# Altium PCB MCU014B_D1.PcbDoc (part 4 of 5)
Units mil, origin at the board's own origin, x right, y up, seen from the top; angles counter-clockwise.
Board outline 2300.04 x 4058 mil, 4 copper layers (TOP, GND, PWR, BOTTOM), stack 48.84 mil thick; 371 components, 238 nets, 1148 pads, 688 vias.
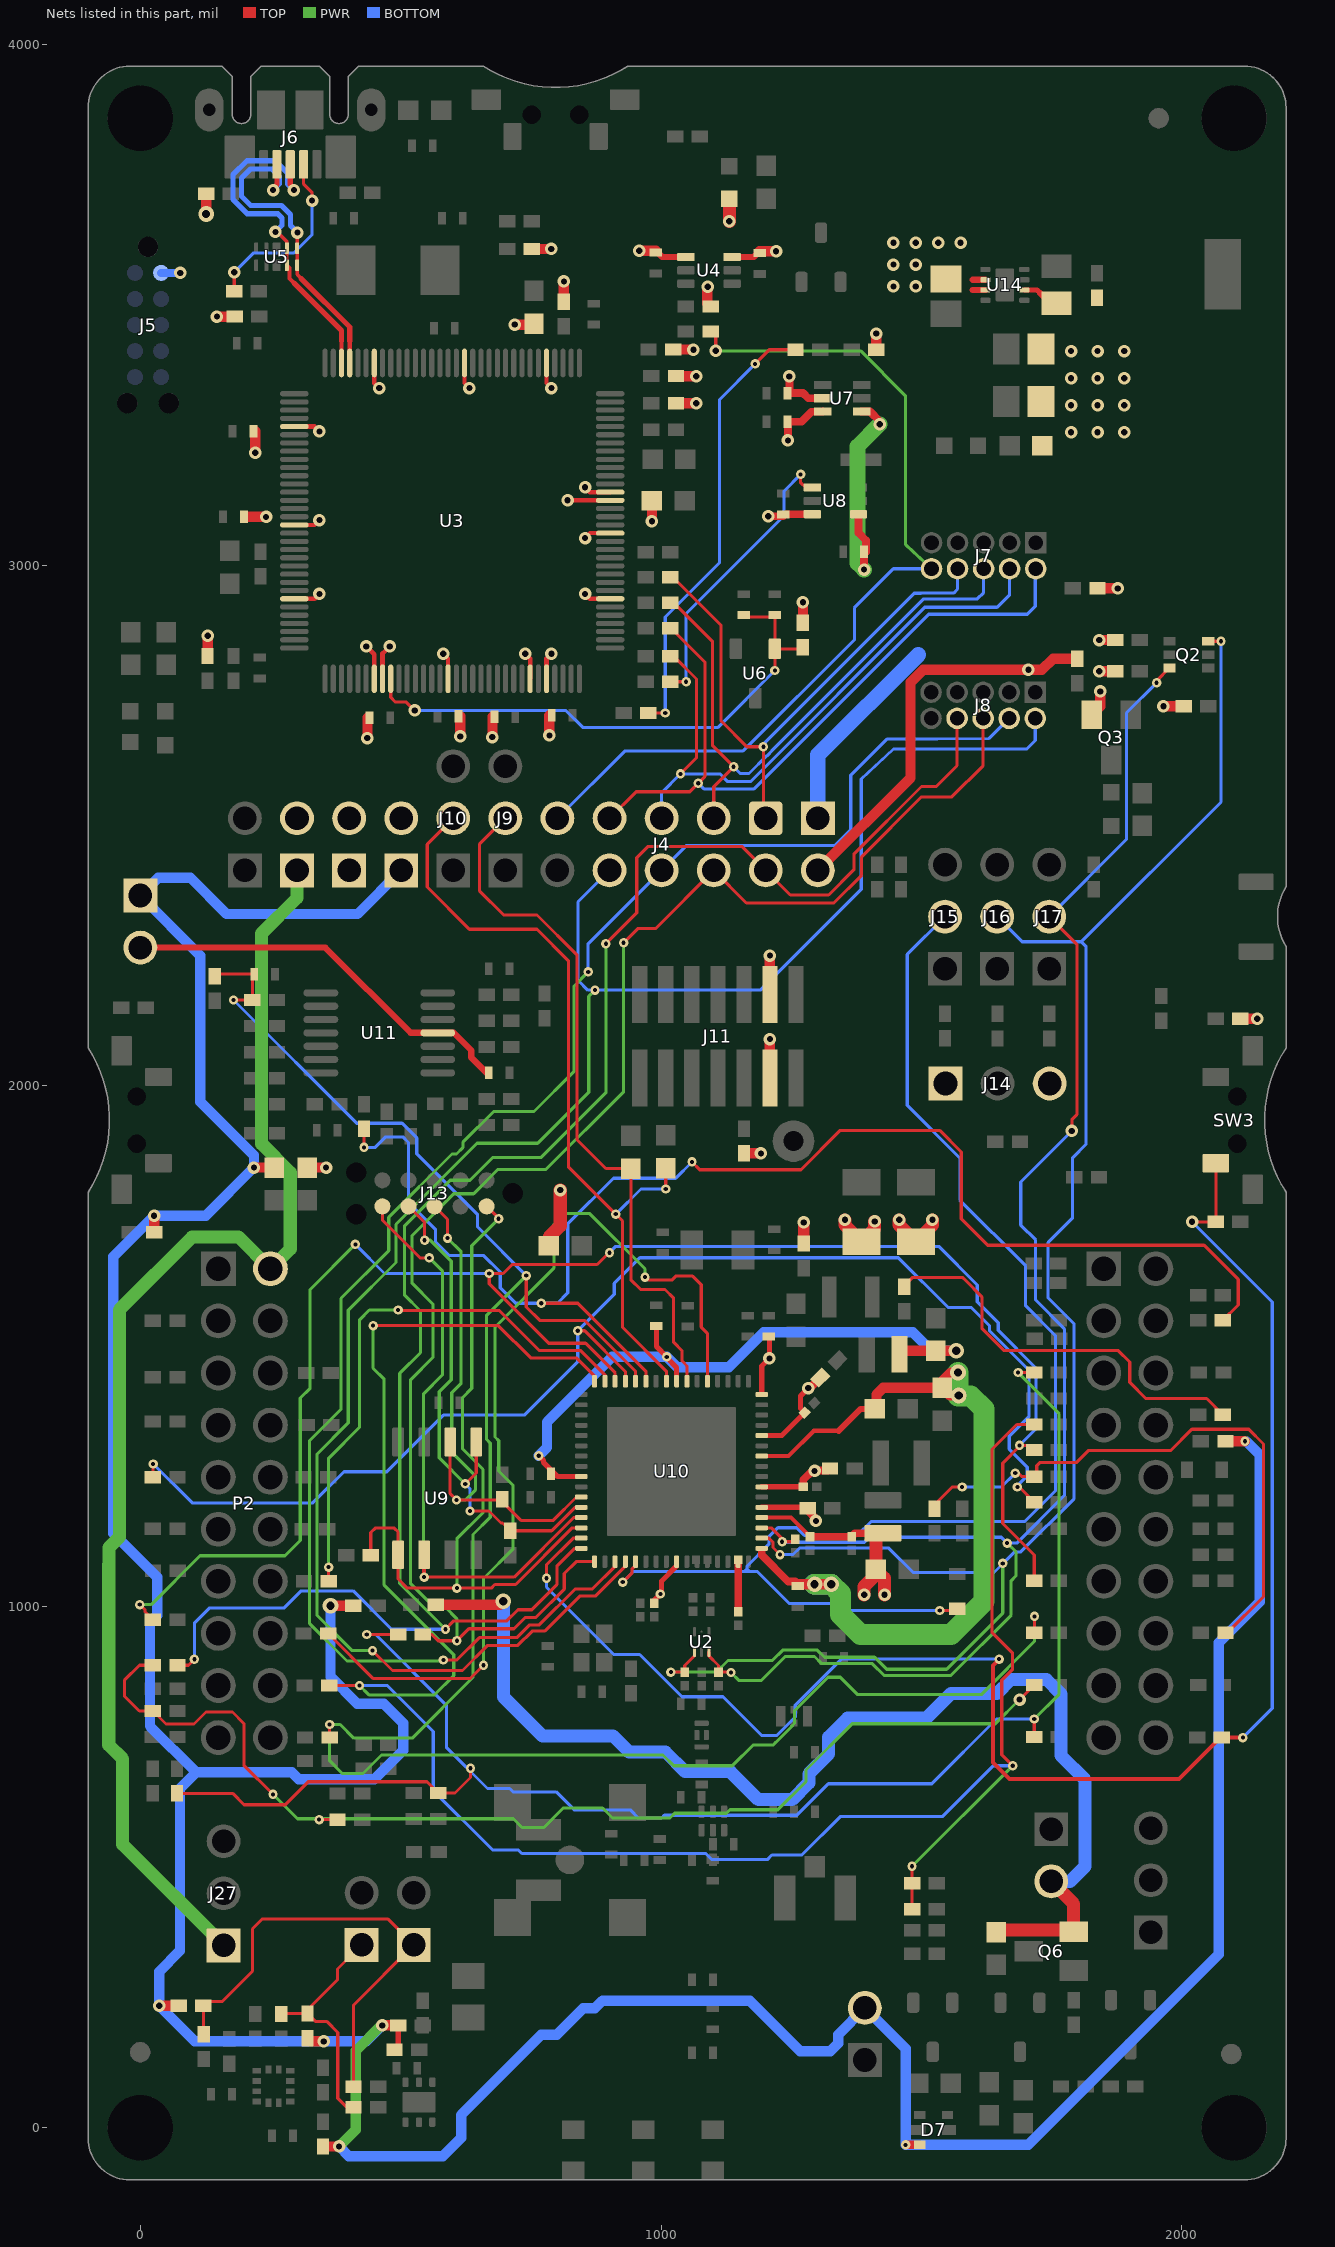
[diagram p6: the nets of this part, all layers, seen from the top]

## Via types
v1: diameter 24, hole 12, TOP to BOTTOM, tented both sides, 230 vias
v2: diameter 18, hole 8, TOP to BOTTOM, tented both sides, 218 vias
v3: diameter 20, hole 10, TOP to BOTTOM, tented both sides, 159 vias
v4: diameter 19.68, hole 7.87, TOP to BOTTOM, 32 vias
v5: diameter 20, hole 8, TOP to BOTTOM, tented both sides, 24 vias
v6: diameter 30, hole 16, TOP to BOTTOM, tented both sides, 17 vias
v7: diameter 20, hole 8, TOP to BOTTOM, tented bottom, 4 vias
v8: diameter 19.68, hole 7.87, TOP to BOTTOM, tented bottom, 4 vias

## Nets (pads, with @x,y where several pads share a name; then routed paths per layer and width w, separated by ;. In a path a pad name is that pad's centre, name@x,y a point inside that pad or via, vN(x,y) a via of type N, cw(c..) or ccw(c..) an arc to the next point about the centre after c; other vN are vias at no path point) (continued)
P15_GPIO_22: R95.2 R157.1 SW3.3 U10.15 | length 3157.5
  TOP w6: v2(780,1055) 780,1081 831.05,1132.05 U10.15@846.77,1132.05 ; v1(2019.38,1739.21) R157.1@2065.02,1739.21 SW3.3@2065.02,1851.92
  TOP w8: v2(1648.92,899.64) 1637,887.72 1637,701.43 1669.21,669.21 1994.21,669.21 2073.99,748.99 R95.2@2076.62,748.99 v2(2117,748.99)
  BOTTOM w6: v2(780,1055) 780,1037.78 909.2,908.58 958.85,908.58 1040,827.43 1118.93,827.43 1193.62,752.75 1221.64,752.75 1257.48,788.59 1257.48,811.22 1345.9,899.64 v2(1648.92,899.64) ; v1(2019.38,1739.21) 2173.35,1585.25 2173.35,805.34 v2(2117,748.99)
P16_GPIO_23: R50.2 R90.1 R108.1 R135.1 | length 2192
  TOP w6: R50.2@24.38,888 -1.31,888 -30.39,858.92 -30.39,828.81 -1.7,800.11 24.27,800.11 R108.1@24.38,800 49.38,775 103.2,775 126.2,798 177,798 199,776 199,696 v2(255,640) ; v2(343.38,591.52) R135.1@378.76,591.52 ; v1(1688.19,822.05) 1688.43,822.05 R90.1@1716.38,850
  PWR w6: v2(255,640) 301.93,593.07 716.7,593.07 733.6,576.17 774.55,576.17 812.06,613.68 887.7,613.68 906.78,594.59 1017.07,594.59 1026.15,603.67 1125.51,603.67 1132.35,610.52 1224.19,610.52 1278.19,664.52 1278.19,686.9 1366.84,775.55 1641.69,775.55 v1(1688.19,822.05)
P16_JTAG_TDI: J4.2 J8.8 R50.1 U10.16 | length 3672.8
  TOP w6: R50.1@71.62,888 92.65,888 v2(103.93,899.28) ; v2(586,957) 602,973 703.91,973 725.23,994.32 751.72,994.32 800,1042.6 800,1078 834.36,1112.36 U10.16@846.77,1112.36 ; v2(894,2273) 953.37,2332.37 953.37,2438.37 975,2460 1155,2460 J4.2@1201,2414 1248.27,2366.73 1321.73,2366.73 1370,2415 1370,2445 1500,2575 1528.24,2575 1568.24,2615 J8.8@1568.24,2705.73
  PWR w6: v2(586,957) 498.21,1044.79 498.21,1448.21 538,1488 538,1568 507,1599 507,1731 595,1819 633.14,1819 677.14,1863 770,1863 894,1987 v2(894,2273)
  BOTTOM w6: v2(103.93,899.28) 103.93,968.75 133.18,998 276.52,998 309.19,1030.67 408.69,1030.67 482.36,957 v2(586,957)
P17_GPIO_24: R54.2 R70.1 R94.1 R109.1 R142.1 | length 3026.1
  TOP w6: R109.1@70.4,641.89 177.43,641.89 199.33,620 278.43,620 322.64,664.21 550.55,664.21 R142.1@572.24,642.52 604.28,642.52 634.09,672.33 v2(634.09,690) ; v2(435,947) R54.2@495,947 ; v2(1685.45,1450) R70.1@1716.38,1450 ; R94.1@1716.38,750 v2(1716.38,784.6)
  PWR w6: v2@1685.45,1449.13 1764.17,1370.41 1764.17,832.39 v2(1716.38,784.6)
  BOTTOM w6: v2(435,947) 451.84,947 587.67,811.16 587.67,730.33 666.79,651.21 709.18,651.21 715.66,644.74 798.39,644.74 832.94,610.19 940.81,610.19 956.62,594.39 1000.84,594.39 1006.36,599.91 1260.74,599.91 1321.25,660.42 1519.8,660.42 1643.97,784.6 v2(1716.38,784.6)
P17_JTAG_TDO: J4.4 J8.6 R54.1 U10.17 | length 3077.9
  TOP w6: R54.1@542.24,947 560,947 572,935 v2(608,935) 631,958 717.48,958 739.1,979.62 759.62,979.62 814,1034 814,1064 836.77,1086.77 U10.17@872.36,1086.77 ; v2(928,2275) 955.21,2302.21 989.21,2302.21 J4.4@1101,2414 1163.64,2351.36 1331.62,2351.36 1385,2404.75 1385,2440 1500,2555 1558.24,2555 1618.24,2615 J8.6@1618.24,2705.73
  PWR w6: v2(608,935) 608,977 586,999 564.43,999 519.21,1044.22 519.21,1436.21 562,1479 562,1581 522,1621 522,1713 602,1793 640,1793 687,1840 779,1840 928,1989 v2(928,2275)
P19_JTAG_TCK: J4.6 J8.4 U10.19 | length 3325.3
  TOP w6: v2(582,898) 608,898 651,941 723.12,941 747.49,965.37 766.37,965.37 835.22,1034.21 867.82,1034.21 911.73,1078.12 U10.19@911.73,1086.77
  PWR w6: v2(582,898) 580,896 397,896 325.31,967.69 325.31,1319.31 385.34,1379.34 385.34,1592.34 477,1684 477,1747.76 598.68,1869.44 607.19,1869.44 619.49,1881.74 619.49,1891.75 678.75,1951 756,1951 833,2028 833,2192 v2(860,2219)
  BOTTOM w6: v2(860,2219) 860,2273 J4.6@1001,2414 1049,2462 1334.14,2462 1364.21,2492.07 1364.21,2596.57 1433.43,2665.79 1629.85,2667.34 J8.4@1668.28,2705.77
P20_JTAG_TMS: J4.8 J8.2 U10.20 | length 3702.6
  TOP w6: v2(446,916) 484.25,877.75 618.75,877.75 667,926 725.09,926 752.46,953.37 776.31,953.37 843.48,1020.54 873.78,1020.54 931.42,1078.18 U10.20@931.42,1086.77
  PWR w6: v2(446,916) 407,916 339.31,983.69 339.31,1293.31 399.41,1353.41 399.41,1569.41 491,1661 491,1734.42 646.58,1890 763,1890 861,1988 861,2172 v2(873,2184)
  BOTTOM w6: J4.8@901,2414 840.57,2353.57 840.57,2202.89 859.47,2184 v2(873,2184) 1190.58,2184 1384.21,2377.64 1384.21,2589.33 1446.05,2647 1701.9,2647 1718.28,2663.38 J8.2@1718.28,2705.77
P21_GPIO_25: R55.2 R75.1 R87.2 | length 1123.7
  TOP w6: R55.2@1525,1188.62 1525,1196 1559,1230 v2(1578,1230) ; v2(1679.81,1256.81) 1686.19,1256.81 1693,1250 R75.1@1716.38,1250 1721.1,1250 1721.1,1271.1 1727,1277 1797,1277 1820,1300 1978.09,1300 2019.09,1341 2128.2,1341 2156.66,1312.53 2156.66,1019.63 2087.03,950 R87.2@2083.62,950
  BOTTOM w6: v2(1578,1230) 1653,1230 v2(1679.81,1256.81)
P45_GPIO_31: R47.1 R73.2 | length 787.5
  TOP w6: R47.1@1467,1614.62 1467,1617 1482,1632 1579.39,1632 1583.98,1627.4 1615.89,1595.15 1615.89,1534.77 1658.69,1491.97 1877.78,1491.97 1899.79,1469.96 1899.79,1430.89 1930.54,1400.14 2047.48,1400.14 R73.2@2078.62,1369
P53_GPIO_30: R97.2 U10.53 | length 1830.2
  TOP w6: R97.2@360.62,949 447.52,862.1 633.1,862.1 v2(659,888) ; v2(969,1633) 974.62,1627.38 1020.38,1627.38 1028,1635 1060.53,1635 1077,1618.53 1077,1537 1088.9,1525.1 U10.53@1088.9,1433.23
  PWR w6: v2(659,888) 659,1054.57 716,1111.57 716,1233 688.21,1260.79 688.21,1318.91 681,1326.13 681,1537 794.21,1650.21 794.21,1734.21 815,1755 863,1755 969,1649 v2(969,1633)
P55_GPIO_01: J9.2 R39.1 U10.55 | length 1359.7
  TOP w6: J9.2@701,2514 651,2464 651,2375.1 697.69,2328.41 761.81,2328.41 838.21,2252.01 838.21,1897.21 893.92,1841.5 R39.1@942,1841.5 942,1628 960.63,1609.37 1007.36,1609.37 1024,1592.74 1024,1508 1040,1492 1040,1472.26 1045.84,1466.42 1045.84,1466.16 1049.53,1462.47 U10.55@1049.53,1433.23
P57_GPIO_02: J10.2 R38.1 U10.57 | length 1523.9
  TOP w5.98: 822,1845 822,2240.73
  TOP w6: J10.2@601,2514 551,2464 551,2381.98 631.96,2301.01 761.71,2301.01 822,2240.73 ; 822,1845 v2(913,1754) 926,1741 926,1536.72 1010.16,1452.56 U10.57@1010.16,1433.23 ; v2(1009,1802.32) R38.1@1009,1842.5
  BOTTOM w6: v2(913,1754) 961.32,1802.32 v2(1009,1802.32)
P59_GPIO_04: R65.2 R125.2 U10.59 | length 2739.8
  TOP w6: v2(429.54,1882.2) 429.64,1882.3 R125.2@429.64,1917.76 ; v2(770,1583) 840.12,1583 970.79,1452.33 U10.59@970.79,1433.23 ; v2(1059.21,1854.21) 1074.21,1839.21 1268.51,1839.21 1344.06,1914.76 1534.66,1914.76 1576.21,1873.21 1576.21,1745 1627,1694.21 2042.58,1694.21 2108.14,1628.66 2108.14,1579.52 R65.2@2078.62,1550
  BOTTOM w6: v2(429.54,1882.2) 451.24,1882.2 471.42,1902.38 503.93,1902.38 514.92,1891.38 514.92,1776.53 567.16,1724.28 567.16,1700.61 593.56,1674.21 659.83,1674.21 691.15,1642.89 691.15,1612.46 720.61,1583 v2(770,1583) 801.03,1583 820.79,1602.76 820.79,1735.25 908.49,1822.95 1027.95,1822.95 v2(1059.21,1854.21)
P60_GPIO_05: C71.1 R86.1 R106.2 R113.1 R114.2 U10.60 | length 4170.6
  TOP w6: R113.1@143,2210.62 147.38,2215 215.38,2215 R114.2@215.38,2165 v2(179,2165) ; R106.2@363.62,749 v2(363.62,774.21) ; v2(741.02,1636) 741.02,1575.72 766.73,1550 853.02,1550 951.1,1451.92 U10.60@951.1,1433.23 ; R86.1@1716.38,950 1716.94,950.56 v2(1716.94,981.63)
  PWR w6: v2(741.02,1636) 665,1560 665,1321.43 672,1314.43 672,1171.8 639,1138.8 639,864.73 522.15,747.88 410.21,747.88 383.88,774.21 v2(363.62,774.21) 363.62,704.26 387.74,680.14 427.73,680.14 463.09,715.51 1003.61,715.51 1024.25,694.87 1136.68,694.87 1176.37,734.56 1214.73,734.56 1220.25,740.08 1220.59,740.08 1249.7,769.19 1249.7,769.53 1256.18,776.01 1256.18,800.53 1320.52,864.87 1344.16,864.87 1377.66,831.37 1614.58,831.37 1716.94,933.73 v2(1716.94,981.63)
  BOTTOM w6: v2(179,2165) 415.48,1928.52 502.87,1928.52 530.89,1900.49 530.89,1869.8 647.85,1752.84 647.85,1729.16 v2(741.02,1636)
P61_GPIO_06: R84.1 R107.1 U10.61 | length 2525.5
  TOP w6: R84.1@24.81,1249.03 v2(24.81,1274.24) ; v2(840,1530) 853.2,1530 931.42,1451.78 U10.61@931.42,1433.23 ; v2(1684,1230) 1687.38,1230 R107.1@1716.38,1201
  BOTTOM w6: v2(24.81,1274.24) 99.52,1199.53 331.3,1199.53 391.11,1259.35 473.35,1259.35 582,1368 737.28,1368 840,1470.72 ; 840,1470.08 840,1470.72 ; v2@1685,1230 v2(1684,1230) 1684,1232.72 1703,1251.72 1703,1268.28 1668.45,1302.83 1668.45,1327.67 1706.59,1365.81 1706.59,1453.89 1630.82,1529.66 1630.82,1539.22 1595.05,1575 1550.93,1575 1455.62,1670.31 959.32,1670.31 910,1621 910,1600.01 v2(840,1530) 840,1470.72
P62_GPIO_07: R82.1 R96.1 R103.1 U10.62 | length 3326.2
  TOP w6: v2(-0.79,1004.21) 9.4,994.03 9.4,989.98 R96.1@24.38,975 ; v2(901,1680) 900,1680 877.21,1657.21 713.93,1657.21 696.72,1640 v2(670,1640) 670,1620 784,1506 855,1506 911.7,1449.3 U10.62@911.73,1433.23 ; R82.1@1716.38,1050 1716.38,1099.62 1656,1160 1656,1276 1690,1310 1707.38,1310 R103.1@1716.38,1301
  PWR w6: v2(-0.79,1004.21) 21.01,1004.21 114.8,1098 278,1098 307.31,1127.31 307.31,1400.91 326.21,1419.81 326.21,1609.21 v2(413,1696)
  BOTTOM w6: v2(413,1696) 469,1640 v2(670,1640) ; v2(901,1680) 913,1692 1533,1692 1607,1618 1607,1585.82 1647.25,1545.57 1647.25,1530.79 1719.82,1458.22 1719.82,1341.82 v2(1688,1310)
P63_GPIO_08: R93.2 U10.63 | length 1069.6
  TOP w6: R93.2@361.62,1049 v2(361.62,1076.38) ; v2(495,1570) 496,1569 689.42,1569 766.42,1492 846,1492 892.05,1445.95 U10.63@892.05,1433.23
  PWR w6: v2(361.62,1076.38) 361.62,1285.62 421.21,1345.21 421.21,1551.21 440,1570 v2(495,1570)
P64_GPIO_09: R72.1 R99.2 R168.1 R171.1 U10.64 | length 4105.4
  TOP w6: R99.2@362.62,849 v2(421,849) ; v2(447,1540) 687.43,1540 749.43,1478 837.08,1478 872.33,1442.75 U10.64@872.33,1433.23 ; R168.1@1481.81,419.21 R171.1@1481.81,469.21 v2(1481.81,502.06) ; v2(1675,695) 1654,716 1654,859 1675,880 1675,910.96 1635,950.96 1635,1302 1683,1350 R72.1@1716.38,1350
  PWR w6: v2(421,849) 439,831 565,831 602,868 602,908 468.21,1041.79 468.21,1437.21 447,1458.43 v2(447,1540) ; v2@1481.81,501.81 v2(1675,695)
  BOTTOM w6: v2(421,849) 474.16,849 562.56,760.6 562.56,647.22 676.73,533.05 726.01,533.05 732.59,526.46 1085.9,526.46 1097.73,514.64 1203.93,514.64 1212.76,523.47 1270.03,523.47 1343.74,597.18 1539.97,597.18 1637.79,695 v2(1675,695)
RF_BG: pad.2@1148.06,1090.22 R1.2 U10.31 | length 99.5
  TOP w15: R1.2@1148.06,990.76 1147.95,990.87 U10.31@1147.95,1086.77 1147.95,1090.11 pad.2@1148.06,1090.22
SENS_I2C_SCL: J19.1 R134.2 R147.1 R149.1 | length 462.3
  TOP w5.98: 379.21,111.79 379.21,56.34 396.18,39.37 R149.1@409.45,39.37
  TOP w6: R147.1@271,218.24 272,219.24 R134.2@321,219.24 ; 379.21,111.79 379.21,182.83 357.96,204.08 336.16,204.08 R134.2@321,219.24 ; J19.1@425,351 378.65,304.65 378.65,284.06 321,226.41 R134.2@321,219.24
SENS_I2C_SDA: J20.1 R133.2 R145.1 R148.1 | length 916.3
  TOP w5.98: R148.1@409.64,78.93 409.64,131.83
  TOP w6: R145.1@122,179.24 121.1,180.14 R133.2@121.1,234 129.53,242.43 157.43,242.43 215.66,300.66 215.66,381.81 234.86,401 475,401 J20.1@525,351 409.64,235.64 409.64,131.83
SFL_CLK: J13.8 R45.1 U9.6 U10.11 | length 1037.8
  TOP w6: J13.8@565,1769 590,1744 v2(590,1708) ; U9.6@595,1316.49 595,1217.4 v2(607.24,1205.16) 691.65,1205.16 R45.1@695,1201.81 ; R45.1@690.8,1210.58 R45.1@695,1206.38 R45.1@695,1201.81 ; U10.11@846.77,1210.79 837.67,1210.79 792.86,1165.98 730.83,1165.98 R45.1@695,1201.81
  PWR w6: v2(590,1708) 616,1682 616,1429 598,1411 598,1297 644,1251 644,1225 624.16,1205.16 v2(607.24,1205.16)
SFL_CS: J13.10 R44.2 U9.1 U10.14 | length 1407.8
  TOP w6: R44.2@442.62,1099 442.62,1142.62 451.11,1151.11 487.91,1151.11 495,1144.03 U9.1@495,1099.95 495,1053.62 512.62,1036 v2(608,1036) 673.8,1036 680.8,1043 720.8,1043 829.53,1151.73 U10.14@846.77,1151.73 ; J13.10@665,1769 688,1746 v2(688,1745)
  PWR w6: v2(608,1036) 608,1130.72 658,1180.72 658,1264 619,1303 619,1402 636.41,1419.41 636.41,1693.41 v2(688,1745)
SFL_DIN: J13.6 U9.2 U10.13 | length 1177.1
  TOP w6: J13.6@465,1769 465,1742.15 537.15,1670 v2(555,1670) ; v2(545,1057) 717.83,1057 832.25,1171.42 U10.13@846.77,1171.42
  TOP w8: v2(545,1057) U9.2@545,1099.95
  PWR w6: v2@544,1057 544,1409.2 580,1445.2 580,1645 v2(555,1670)
SFL_DOUT: J13.7 R46.1 U9.5 U10.12 | length 996.6
  TOP w6: J13.7@515,1769 546,1738 v2(546,1704) ; v2(624,1236) 645,1257 U9.5@645,1316.49 ; v2(633,1184) 669.53,1184 692.57,1160.96 695.57,1160.96 R46.1@710.53,1146 789.86,1146 834.96,1191.1 U10.12@846.77,1191.1
  PWR w6: v2(546,1704) 556.76,1704 597,1663.76 597,1436 574,1413 574,1286 v2(624,1236)
  BOTTOM w6: v2(624,1236) 633,1227 v2(633,1184)
SOP0: C14.1 C68.1 J17.2 Q2.3 U2.6 U10.35 | length 3307.1
  TOP w6: U2.6@1091.58,912.93 1091.58,905.99 1110.31,887.27 C14.1@1110.31,874.7 1136.91,874.7 1136.18,873.98 v2(1134.32,873.98) ; U10.35@1193.23,1151.73 1211.76,1151.73 1232.4,1131.09 v2(1232.4,1124.92) 1252.43,1124.92 C68.1@1257.24,1129.73 ; J17.2@1745.12,2325.12 1798.3,2271.94 1798.3,1945 1788.62,1935.32 v1(1788.62,1913.62) ; v2(1951.3,2774.2) 1951.3,2778.01 Q2.3@1975.9,2802.61
  PWR w6: v2(1134.32,873.98) 1149.93,858.37 1191.74,858.37 1238.04,904.67 1294.58,904.67 1308.21,891.04 1405.46,891.04 1428.41,868.09 1555.99,868.09 1671.97,984.07 1671.97,1050.23 1681.25,1059.51 1681.25,1105.49 v2(1664.35,1122.39)
  BOTTOM w6: v2@1233.76,1130.82 1240.43,1124.15 1389.96,1124.15 1399.34,1133.52 1653.22,1133.52 v2(1664.35,1122.39) 1682.78,1122.39 1774.25,1213.86 1774.25,1533.75 1719,1589 1719,1704.49 1690.55,1732.94 1690.55,1815.56 v1(1788.62,1913.62) ; J17.2@1745.12,2325.12 1893.5,2473.5 1893.5,2716.4 v2(1951.3,2774.2)
SOP1: C15.1 J16.2 Q2.6 U2.4 U10.34 | length 3602.7
  TOP w6: v2(1018.71,874.7) C15.1@1045.31,874.7 1045.31,887.27 1064.03,905.99 U2.4@1064.03,912.93 ; U10.34@1193.23,1132.05 1206.86,1132.05 1214.79,1124.12 1214.79,1113.83 v2(1228.23,1100.39) ; Q2.6@2050.7,2853.79 v2(2075.02,2853.79)
  PWR w6: v2(1018.71,874.7) 1106.13,874.7 1128.54,897.11 1213.43,897.11 1233.32,917 1299.97,917 1313.83,903.14 1409.91,903.14 1432.9,880.14 1548.25,880.14 1655.98,987.87 v2(1655.98,1083.52)
  BOTTOM w6: v2(1228.23,1100.39) 1253.22,1100.39 1265.66,1112.82 1437.09,1112.82 1483.91,1066 1639.22,1066 1678.7,1105.48 1690.76,1105.48 1792.99,1207.7 1792.99,1543.02 1743,1593 1743,1699.72 1790.15,1746.87 1790.15,1862.31 1815.61,1887.77 1815.61,2268.27 1806.99,2276.89 ; J16.2@1645.12,2325.12 1693.35,2276.89 1806.99,2276.89 ; v2(2075.02,2853.79) 2075.02,2544.92 1806.99,2276.89
SOP2: D4.2 J15.2 U10.21 | length 2681.6
  TOP w6: v2(926.27,1047.58) 944.42,1065.73 944.42,1073.35 951.1,1080.03 U10.21@951.1,1086.77 ; v2(1535,993) 1565.69,993 D4.2@1568.87,996.17
  BOTTOM w6: v2(926.27,1047.58) 946.69,1068 1159.63,1068 ; v2(1535,993) 1534.75,992.75 1355.81,992.75 1342.38,1006.18 1246.46,1006.18 1184.63,1068 1170.37,1068 ; J15.2@1545.12,2325.12 1472.69,2252.69 1472.69,1962.69 1573.54,1861.85 1573.54,1780.85 1699.8,1654.59 1699.8,1648.25 1699.84,1648.2 1699.84,1634.12 1699.8,1634.07 1699.8,1578.21 1757.28,1520.72 1757.28,1222.78 1698.5,1164 1403.21,1164 1376.59,1137.38 1275.03,1137.38 1260.49,1151.92 1224.09,1151.92 1206.89,1134.72 1206.89,1119.89 1165,1078 1165,1073.37 ; 1159.63,1068 1165,1068 ; 1159.63,1068 1165,1073.37 ; 1165,1068 1170.37,1068 ; 1165,1068 1165,1073.37 ; 1165,1073.37 1170.37,1068
VBAT_CC: C42.1 C43.1 C44.1 C45.1 C46.1 C81.1 C82.1 J11.3 J11.4 J12.2 J14.1 J24.1 Q6.2 R37.2 R40.2 R43.2 R48.2 R64.1 R166.2 U10.37 U10.39 U10.44 | length 3349.7
  TOP w10: U10.37@1193.23,1191.1 1279.78,1191.1 C42.1@1281.38,1189.5 ; U10.39@1193.23,1230.47 C44.1@1272.79,1230.47 ; U10.44@1193.23,1328.9 1231.58,1328.9 C46.1@1275.68,1373 1267.51,1381.17 1267.51,1404.91 v1(1282.74,1420.13)
  TOP w15.01: C44.1@1272.79,1230.47 1272.79,1243.72 1290.02,1260.95 v1(1294.56,1260.95) 1295.4,1261.79 1320.39,1261.79 C43.1@1324.29,1265.69 ; C42.1@1281.38,1189.5 1281.38,1184.5 1297.32,1168.55 v1(1297.32,1165.01) ; v1(1282.74,1420.13) 1285.75,1420.13 C45.1@1305.62,1440
  TOP w19.9: R64.1@321,1843.5 v1(356.7,1843.5) ; R43.2@567.01,1004 690,1004 v6(697,1011) ; R37.2@1159.21,1870.59 v1(1191.67,1870.59)
  TOP w20: J11.4@1209,2015.2 v1(1209,2090.12) ; J11.3@1209,2175.43 v1(1209,2250.35)
  TOP w22: R48.2@1274,1697.62 v1(1274,1738)
  TOP w25: R40.2@784.5,1693 784.5,1709.5 806.38,1731.38 v1(806.38,1800.18) ; v1(1353,1743) 1353,1732.91 C82.1@1385,1700.91 1410,1725.91 v1(1410,1740) ; v1(1457,1743) 1457,1732.91 C81.1@1489,1700.91 1521,1732.91 v1(1521,1743) ; R166.2@1643.9,375.72 1647.59,379.41 1789.42,379.41 Q6.2@1792.2,376.63 1792.2,429.8 J12.2@1749,473
  BOTTOM w25: v6(697,1011) 697,827.29 771.96,752.33 907.57,752.33 938.64,721.25 1008.51,721.25 1046.07,683.7 1133.01,683.7 1186.75,629.96 1251.68,629.96 1283.73,662 1283.73,679.28 1321.8,717.36 1321.8,750.17 1358.01,786.38 1509.15,786.38 1556.16,833.39 1644.74,833.39 1671.83,860.47 1739.89,860.47 1767.37,833 1767.37,714.66 1814,668.03 1814,501.67 1785.33,473 J12.2@1749,473
VBUS_USB1: C80.1 J23.2 L5.2 R8.1 R15.1 U14.2 U14.3 | length 161.1
  TOP w12: 1598.13,3528.16 U14.3@1622.6,3528.16 ; 1598.43,3547.84 U14.2@1622.6,3547.84
  TOP w20: v6(126.38,3674.04) L5.2@126.38,3713 ; R15.1@129,2825.62 129.38,2826 v1(129.38,2864.62) ; v1(147.21,3477.21) R8.1@181.59,3477.21
  other v1: 1446,3535 1489,3535 1446,3577 1489,3577 1446,3619 1489,3619 1532,3619 1575,3619
VCC_5V: J23.1 J27.1 P2.2 | length 2524.6
  PWR w25: J27.1@160,350 -33.84,543.84 -33.84,708.22 -60.46,734.83 -60.46,1080.83 -60.29,1081 -60.29,1113.65 -40.09,1133.84 -40.09,1570.14 99.76,1710 188.91,1710 P2.2@249.91,1649 288,1687.09 288,1834 233.21,1888.79 233.21,2293.21 301,2361 J23.1@301,2414
VCC_BRD: D7.1 J14.3 J18.1 J21.1 J22.2 J25.2 Q3.2 R35.1 R42.2 R66.1 R130.2 R131.2 R133.1 R134.1 R138.2 R150.1 R151.1 R152.1 R153.2 R154.2 R155.2 | length 9252.5
  TOP w10: R130.2@488.19,149.61 495.3,156.72 R138.2@495.3,196.35
  TOP w15.75: v2@1469.81,-32.87 D7.1@1496.77,-32.87
  TOP w19.9: R150.1@26.62,1719 v1(26.62,1750.81) ; v1(218.3,1843.5) R66.1@257,1843.5 ; v6(365.31,1002) R42.2@408.68,1002 ; J22.2@1301,2414 1478.95,2591.95 1478.95,2774.89 1502.97,2798.91 v1(1705.21,2798.91) ; Q3.2@1826.81,2712.52 1843.15,2728.86 v1(1843.15,2757.55) ; R152.1@2083.62,1318 v2(2121,1318) ; R151.1@2112.26,2129.21 v1(2144.72,2129.21)
  TOP w20: v1(36.38,234) R133.1@73.86,234 ; R134.1@321,172 327,166 351.83,166 v1(352.1,165.72) ; R131.2@351,-36 v1(381.62,-36) ; v1(464.73,196.35) R138.2@495.3,196.35 ; v1(1705.21,2798.91) 1731.11,2798.91 1752.82,2820.62 R35.1@1799.13,2820.62 ; v1(1841.3,2796.2) R153.2@1871.68,2796.2 ; v1(1841.3,2856.2) R155.2@1871.68,2856.2 ; v1(1964.44,2729.21) R154.2@2003.46,2729.21
  PWR w19.84: 414.44,148.24 v1@463.64,197.45
  PWR w20: v1(381.62,-36) 414.09,-3.53 414.09,148.24
  BOTTOM w19.9: v6(365.31,1002) 365.31,865.67 416.77,814.21 467.72,814.21 505,776.94 505,725 449.21,669.21 303.91,669.21 290.91,682.21 107.63,682.21 ; v1(464.73,196.35) 434.1,165.72 v1(352.1,165.72) 104.65,165.72 v1(36.38,234) 36.38,299.67 76.26,339.55 76.26,650.85 107.63,682.21 ; J21.1@501,2414 417.13,2330.13 166.38,2330.13 96.5,2400.01 34.51,2400.01 J18.1@0.21,2365.71 115.56,2250.37 115.56,1969.87 218.3,1867.12 v1(218.3,1843.5) 125.61,1750.81 v1(26.62,1750.81) -51.93,1672.26 -51.93,1141.15 32.65,1056.57 32.65,983.96 18.63,969.94 18.63,771.21 107.63,682.21 ; J25.2@1391.23,230.06 1469.51,151.78 v2(1469.51,-32.87) 1704.78,-32.87 2070.5,332.85 2070.5,930.86 2149.28,1009.63 2149.28,1291.72 2123,1318 v2(2121,1318)
  BOTTOM w20: v1(381.62,-36) 400.49,-54.87 580.66,-54.87 616.17,-19.35 616.17,24.45 770.08,178.36 799.5,178.36 850.62,229.47 872.86,229.47 887.43,244.04 1170.04,244.04 1266.98,147.1 1324.61,147.1 1340,162.49 1340,178.83 J25.2@1391.23,230.06
VCC_BUFFER: C19.1 C28.1 C41.1 D3.2 J22.1 R14.1 R33.1 U4.1 U7.1 U7.5 U8.1 | length 1166.9
  TOP w12: C19.1@990,3603.62 1002.03,3591.59 U4.1@1047.71,3591.59
  TOP w15.01: v1(1246.22,3362.22) 1246.22,3330.41 1272.6,3330.41 1282.5,3320.51 1310.1,3320.51 U7.5@1310.2,3320.41 ; U8.1@1379,3097.82 1379,3061.98 1393.22,3047.76 1393.22,3025.41 1389.6,3021.79 v1(1389.6,2991.41) ; U7.1@1385,3294.82 1401.19,3294.82 1419.6,3276.41 v1(1419.6,3270.41)
  TOP w19.9: R33.1@1413.22,3413.41 v1(1413.22,3444.51)
  TOP w20: v1(958.19,3603.62) C19.1@990,3603.62 ; v1@1088.96,3534.64 1088.96,3502.61 R14.1@1094.95,3496.62
  TOP w25: v1(1131,3660) D3.2@1131,3703.2
  PWR w30: v1(1389.6,2991.41) 1377.04,3003.97 1377.04,3227.85 v1(1419.6,3270.41)
  BOTTOM w30: J22.1@1301,2514 1301,2636.14 1493.64,2827.73
  other v1: 1089.34,3534.26
VCC_LDO_3V3: C18.1 C26.1 C29.1 C30.1 C31.1 C32.1 C33.1 C34.1 C35.1 C36.1 C40.1 C78.1 C79.1 J5.1 J21.2 J24.2 L12.2 R22.1 R23.1 R24.1 R26.1 R28.2 R31.1 R32.1 R160.1 R161.2 U3.7 U3.8 U3.16 U3.26 U3.28 U3.39 U3.47 U3.51 U3.52 U3.69 U3.79 U3.90 U3.101 U3.113 U3.122 U4.6 U7.6 U8.6 U14.6 | length 1822.8
  TOP w7.5: U3.113@295.85,3077.13 334.63,3077.13 v1(344,3086.5) ; v1(581.76,2830) 591.13,2820.63 U3.16@591.13,2781.85 ; U3.79@622.62,3388.15 622.62,3349.37 v1(631.99,3340) ; U3.69@780.1,3388.15 780.1,3349.37 v1(789.47,3340) ; v1(854,3052.01) 863.37,3061.38 U3.47@902.15,3061.38
  TOP w9: U3.122@295.85,2935.39 334.63,2935.39 v1(344,2944.76) ; U3.101@295.85,3266.1 334.63,3266.1 v1(344,3256.73) ; v1(434,2844) 449.39,2828.61 U3.7@449.39,2781.85 ; U3.90@449.39,3388.15 449.39,3349.37 v1(458.76,3340) ; U3.8@465.14,2781.85 465.14,2830.24 v1(478.9,2844) ; v1(739.24,2830) 748.61,2820.63 U3.26@748.61,2781.85 ; U3.28@780.1,2781.85 780.1,2820.63 v1(789.47,2830) ; v1(820.37,3124.37) U3.51@902.15,3124.37 ; v1(854,2944.76) 863.37,2935.39 U3.39@902.15,2935.39 ; v1(854,3149.49) 863.37,3140.12 U3.52@902.15,3140.12
  TOP w9.84: U14.6@1697.4,3528.16 1721.84,3528.16 1728,3522
  TOP w12: U4.6@1136.29,3591.59 1177.97,3591.59 C18.1@1189,3602.62 ; 1728,3522 1747.43,3502.57 L12.2@1759,3502.57
  TOP w15.01: v1(1205.6,3093.79) 1234.6,3093.79 1238.63,3097.82 U8.6@1290.42,3097.82 ; v1(1243.6,3239.41) 1243.6,3272.79 1246.22,3275.41 1269.6,3275.41 1288.6,3294.41 1309.79,3294.41 U7.6@1310.2,3294.82
  TOP w20: C30.1@202.62,3093 203,3092.62 v1(241.62,3092.62) ; C31.1@221,3257 221,3216.76 v1@221.38,3216.38 ; v1(436,2668) 436.38,2668.38 C35.1@436.38,2707 ; v1(614.24,2671) 614.62,2671.38 C34.1@614.62,2710 ; v1(676,2670) 676.38,2670.38 C36.1@676.38,2709 ; v1(719,3461.87) 754.37,3461.87 C32.1@756,3463.5 ; R26.1@751.62,3607 v1(789,3607) ; v1(785.62,2673) 785.62,2711.24 C29.1@786.38,2712 ; R32.1@813,3505.62 813.38,3506 v1(813.38,3544.62) ; v1(982.5,3084.32) C33.1@982.5,3124 ; R22.1@1023,3414 1061.62,3414 v1(1062,3413.62) ; R24.1@1028.62,3311 1029,3310.62 v1(1067.62,3310.62) ; R23.1@1028.62,3363 1029,3362.62 v1(1067.62,3362.62) ; C18.1@1189,3602.62 v1(1220.81,3602.62) ; R28.2@1272,2889.62 1272.38,2890 v1(1272.38,2928.62) ; R31.1@1837.86,2955.63 1838.23,2955.25 v1(1876.86,2955.25)
  BOTTOM w15: J5.1@40,3561 v1(77,3561)
  other v1: 221,3216 1787,3255 1838,3255 1889,3255 1787,3307 1838,3307 1889,3307 1787,3359 1838,3359 1889,3359 1787,3411 1838,3411 1889,3411
VCC_OPAMP: C70.1 J18.2 U11.4 | length 772.8
  TOP w12: J18.2@0.21,2265.71 355.29,2265.71 519,2102 U11.4@571.2,2102 601.95,2102 635.63,2068.32 635.63,2054.75 C70.1@665.38,2025
VDD_ANA: C51.1 C52.1 C53.1 C54.1 C55.1 L7.1 U10.25 U10.36 U10.48 | length 639.8
  TOP w8: U10.36@1193.23,1171.42 1249.2,1171.42 C55.1@1285.88,1134.73
  TOP w10: C54.1@986.58,1007.25 986.58,1012.72 v2(998.62,1024.76) 1000.72,1026.86 1000.72,1049.31 1029.84,1078.43 U10.25@1029.84,1086.77 ; U10.48@1193.23,1407.64 1193.23,1462.23 v1(1208,1477) 1208,1514.38 C52.1@1207,1515.38
  TOP w15.01: C55.1@1287.1,1134.73 C53.1@1365.68,1134.73 1372.33,1141.38 1412.5,1141.38 L7.1@1426,1141.38
  TOP w25: v1(1390,1023) 1390,1039.24 1412.5,1061.74 C51.1@1412.5,1072 1429,1055.5 v1(1429,1023) ; C51.1@1412.5,1077 L7.1@1412.5,1141.38
VDD_DIG: C59.1 C60.1 C61.1 L10.1 U10.9 U10.56 | length 1290.5
  TOP w10: v2(765,1290) 774.13,1280.87 774.13,1277.11 801.08,1250.16 U10.9@846.77,1250.16 ; C61.1@991,1535.38 991,1500 v2(1011,1480) 1011,1478.63 1029.84,1459.79 U10.56@1029.84,1433.23
  TOP w19.9: L10.1@1457.62,1485 1464.12,1491.5 C59.1@1527,1491.5 v6(1566.81,1491.5)
  BOTTOM w19.9: v2(765,1290) 781,1306 781,1355 906,1480 v2(1011,1480) 1030.95,1460.05 1130.05,1460.05 1196.98,1526.98 1483.02,1526.98 1518.5,1491.5 v6(1566.81,1491.5)
VDD_PA: C56.1 C57.1 C58.1 U10.33 U10.42 | length 1592.1
  TOP w8: U10.42@1193.23,1289.53 1244.57,1289.53 1293.04,1338 1341,1338
  TOP w12: 1341,1338 1383,1380 C56.1@1410.5,1380
  TOP w15.01: U10.33@1193.23,1109.37 1193.23,1099.4 1244.19,1048.44 1257.62,1048.44 C58.1@1262.64,1043.42
  TOP w19.9: C57.1@1539,1420.5 1539,1432 1557,1450 v6(1570,1450)
  TOP w20: C58.1@1262.64,1043.42 v6(1294.67,1043.42) v6(1326.7,1043.42) ; C56.1@1410.5,1380 1413.5,1383 1413.5,1407.5 1426.5,1420.5 C57.1@1539,1420.5 ; C57.1@1540,1420.5 1554.79,1405.7 v6(1571.57,1405.7)
  PWR w40: v6(1294.67,1043.42) v6(1326.7,1043.42) 1344.72,1025.4 1344.72,985.33 1383.15,946.89 1556.3,946.89 1619.91,1010.51 1619.91,1379.69 1594.61,1405 1570,1405 1570.7,1405.7 v6(1571.57,1405.7) 1570,1407.27 v6(1570,1450)
  BOTTOM w40: v6(1294.67,1043.42) v6(1326.7,1043.42)
VREFA: C24.1 C25.1 R28.1 U3.9 U6.1 | length 1059
  TOP w6: U3.9@480.89,2781.85 480.89,2746.11 490,2737 511,2737 v1(527,2721) ; C24.1@1159,2900.38 1218,2900.38 1218.4,2899.98 U6.1@1218.4,2839.24 ; v2(1218.4,2797.6) U6.1@1218.4,2839.24 ; R28.1@1272,2842.38 1268.87,2839.24 U6.1@1218.4,2839.24
  BOTTOM w6: v1(527,2721) 817,2721 849.38,2688.62 1109.43,2688.62 v2(1218.4,2797.6)
XDS_JTAG_TCK: J4.5 J7.4 R9.1 | length 1200.2
  TOP w6: R9.1@1017.62,2825 1024.46,2825 1068,2781.46 1068,2630 v2(1037.21,2599.21)
  BOTTOM w6: J4.5@1001,2514 1001,2563 v2(1037.21,2599.21) 1113.21,2599.21 1128.02,2584.4 1171.53,2584.4 1506.2,2919.07 1645.04,2919.07 1669.19,2943.23 J7.4@1669.19,2993.01
XDS_JTAG_TDI: J4.1 J7.8 R12.1 | length 1101.5
  TOP w6: R12.1@1017.62,2977 1022.91,2977 1115,2884.91 1115,2701 1164.76,2651.24 v2(1196.44,2651.24) 1196.44,2519.44 1196,2519 J4.1@1201,2514
  BOTTOM w6: v2(1196.44,2651.24) 1196.44,2655.37 1196,2655.81 1486.14,2945.95 1499.17,2945.95 1499.48,2946.26 1561.53,2946.26 1569.19,2953.93 J7.8@1569.19,2993.01
XDS_JTAG_TDO: J4.3 J7.6 R11.1 | length 1159
  TOP w6: R11.1@1017.62,2928 1023.96,2928 1099,2852.96 1099,2653 v2(1139.21,2612.79) 1101,2574.57 J4.3@1101,2514
  BOTTOM w6: v2(1139.21,2612.79) 1152,2600 1168.78,2600 1203.02,2634.24 1203.48,2634.24 1213.44,2644.2 1213.44,2644.66 1504.04,2935.26 1607.15,2935.26 1619.19,2947.31 J7.6@1619.19,2993.01
XDS_JTAG_TMS: J4.7 J7.2 R10.1 | length 1397.3
  TOP w6: J4.7@901,2514 952,2565 1055,2565 v2(1071.21,2581.21) 1084,2594 1084,2813.95 1018.95,2879 R10.1@1017.62,2879
  BOTTOM w6: v2(1071.21,2581.21) 1082.02,2570.4 1178.58,2570.4 1513.8,2905.63 1703.01,2905.63 1718.24,2920.85 J7.2@1718.24,2992.05
XDS_NRESET: J4.9 J7.10 R17.1 | length 1747.6
  TOP w6: R17.1@1094.95,3448.69 1104.99,3438.66 v1(1104.99,3411.4)
  PWR w6: v1(1104.99,3411.4) 1383.09,3411.4 1469.07,3325.42 1469.45,3039.37 J7.10@1519.19,2993.01
  BOTTOM w6: J4.9@801,2514 930,2643 1156.64,2643 1370.98,2856.24 1370.98,2917.96 1446.03,2993.01 J7.10@1519.19,2993.01
XDS_UART_RX: R5.1 R34.2 | length 862.8
  TOP w6: R5.1@975.62,2716 v2(1008,2716) ; v2(1180.6,3386.41) 1207.6,3413.41 R34.2@1257.98,3413.41
  BOTTOM w6: v2(1008,2716) 1008,2900.36 1112,3004.36 1112,3317.81 v2(1180.6,3386.41)
XDS_UART_TX: R7.1 U8.4 | length 561.8
  TOP w6: R7.1@1017.62,2776 v2(1048,2776) ; v2(1267.94,3174.15) 1267.94,3158.29 1277.23,3149 U8.4@1290.42,3149
  BOTTOM w6: v2(1048,2776) 1048,2907.08 1235.91,3094.99 1235.91,3142.13 v2(1267.94,3174.15)
XDSET_DM: J6.2 U3.93 U5.1 U5.10 | length 645.1
  TOP w7: v1(301.83,3638.43) 301.24,3637.84 U5.1@301.24,3608.55 U5.10@301.24,3575.68 301.24,3558.18 308.94,3550.49
  TOP w8: U3.93@402.15,3388.15 402.15,3430.85 402.28,3430.98
  TOP w10: v1(255,3720) 255,3723.31 262.41,3730.72 J6.2@262.41,3768.63 ; 308.94,3550.49 402.28,3457.15 402.28,3430.98
  BOTTOM w10: v1(255,3720) 267,3732 267,3746.35 252.82,3760.54 211.43,3760.54 194.31,3743.42 194.31,3708.37 212.25,3690.43 271.03,3690.43 288.4,3673.06 288.4,3651.87 v1(301.83,3638.43)
XDSET_DP: J6.3 U3.94 U5.2 U5.9 | length 710
  TOP w7: v1(259.62,3639.67) 262.96,3639.67 281.56,3621.07 U5.2@281.56,3608.55 U5.9@281.56,3575.68 281.56,3575.38 286.57,3570.37 286.57,3550.23 295,3541.8
  TOP w8: 386.28,3430.72 386.4,3430.6 U3.94@386.4,3388.15
  TOP w10: J6.3@288,3768.63 288,3730.66 295,3723.66 v1(295,3720) ; 295,3541.8 386.28,3450.52 386.28,3430.72
  BOTTOM w10: v1(259.62,3639.67) 272.4,3652.46 272.4,3666.44 264.4,3674.43 205.62,3674.43 178.31,3701.74 178.31,3750.05 204.8,3776.54 259.44,3776.54 283,3752.98 283,3732 v1(295,3720)
XDSET_ID: J6.4 R6.1 | length 356.6
  TOP w6: R6.1@180.38,3526 v1(180.38,3562.38) ; J6.4@313.59,3768.63 313.59,3731.41 330,3715 v1(330,3700)
  BOTTOM w6: v1(180.38,3562.38) 217.02,3599.02 294.16,3599.02 330,3634.85 v1(330,3700)
pads on no net: E1.2 E1.3 E1.4 E1.5 FID1.1 FID2.1 FID3.1 FID4.1 FID5.1 FID6.1 J2.2@1354.36,440.99 J2.3@1236.25,440.99 J3.2@764.84,455.16 J3.3@764.84,573.27 J5.7 J5.9 J5.MH1 J5.MH2 J5.MH3 J11.7 J11.8 J13.3 J13.4 J13.5 J13.MH1 J13.MH2 J13.MH3 Label1.0 SH-J3.0 SH-J4.0 SH-J5.0 SH-J6.0 SH-J7.0 SH-J8.0 SH-J9.0 SH-J10.0 SH-J11.0 SH-J12.0 SH-J13.0 SH-J14.0 SH-J15.0 SH-J16.0 SH-J17.0 SH-J18.0 SH-J19.0 SH-J20.0 SH-J21.0 SH-J22.0 SH-J23.0 SW1. SW2. SW3. U3.2 U3.5 U3.6 U3.11 U3.12 U3.13 U3.14 U3.15 U3.18 U3.19 U3.20 U3.21 U3.22 U3.23 U3.24 U3.25 U3.27 U3.29 U3.30 U3.31 U3.32 U3.41 U3.42 U3.43 U3.44 U3.45 U3.46 U3.49 U3.50 U3.53 U3.54 U3.56 U3.57 U3.65 U3.67 U3.71 U3.72 U3.73 U3.74 U3.75 U3.76 U3.77 U3.78 U3.81 U3.82 U3.83 U3.84 U3.85 U3.86 U3.91 U3.92 U3.102 U3.103 U3.104 U3.105 U3.106 U3.107 U3.108 U3.109 U3.110 U3.111 U3.112 U3.116 U3.117 U3.118 U3.119 U3.120 U3.121 U3.123 U3.124 U3.125 U3.126 U3.127 U3.128 U5.3@261.87,3608.55 U5.4 U5.5 U5.6 U5.7 U5.8@261.87,3575.68 U6.3 U10.26 U10.65@925.51,1165.51 U10.65@925.51,1212.76 U10.65@925.51,1260 U10.65@925.51,1307.24 U10.65@925.51,1354.49 U10.65@972.76,1165.51 U10.65@972.76,1212.76 U10.65@972.76,1260 U10.65@972.76,1307.24 U10.65@972.76,1354.49 U10.65@1020,1165.51 U10.65@1020,1212.76 U10.65@1020,1260 U10.65@1020,1307.24 U10.65@1020,1354.49 U10.65@1067.24,1165.51 U10.65@1067.24,1212.76 U10.65@1067.24,1260 U10.65@1067.24,1307.24 U10.65@1067.24,1354.49 U10.65@1114.49,1165.51 U10.65@1114.49,1212.76 U10.65@1114.49,1260 U10.65@1114.49,1307.24 U10.65@1114.49,1354.49 U12.3 U12.7@517.42,48.96 U12.7@552.85,48.96 U13.4 U13.6 U13.10 U14.9@1660,3520.28 U14.9@1660,3555.72

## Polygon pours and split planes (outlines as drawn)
NetC20_1 on TOP "Bottom Layer-NetC2_1" (solid, remove dead copper, pour order 111): 354,2742 364,2752 364,2806 357,2813 257,2813 250,2806 246,2802 108,2802 96,2790 96,2755 109,2742
VCC_LDO_3V3 on TOP "Bottom Layer-VCC_LDO_3V3" (solid, remove dead copper, pour order 113): 1725,3523 1725,3480 1702,3457 1702,3296 1708,3290 1708,3197 1722,3183 1891,3183 1912,3204 1912,3499 1881,3530 1732,3530
VBUS_USB1 on TOP "Bottom Layer-VBUS_USB1" (solid, remove dead copper, pour order 112): 1628,3518 1635,3525 1635,3553 1632,3556 1607,3556 1604,3559 1604,3620 1578,3646 1436,3646 1425,3635 1425,3528 1435,3518
GND on TOP "Top Layer-GND" (solid, remove dead copper, pour order 114): -100,3955 2200,3955 2200,-100 -100,-100
VBUS_USB1 on BOTTOM "Bottom Layer-VBUS_USB1" (solid, remove dead copper, pour order 124): 265.02,2459 353.07,2459.07 360.21,2466.21 360.21,2880.79 317.04,2923.96 317.04,3346.04 461,3490 879,3490 906.34,3517.34 906.34,3615.34 979.08,3688.08 1366.92,3688.08 1406,3649 1406,3527 1430.81,3502.19 1578.19,3502.19 1587.21,3511.21 1587.21,3905.21 1571.21,3921.21 812.21,3921.21 628.21,3737.21 617.99,3726.99 539.45,3726.99 144.92,3726.99 108.37,3690.44 108.37,3276.37 78.01,3246.01 78.01,2746.99 240.04,2584.96 240.04,2483.98
VCC_BUFFER on BOTTOM "Bottom Layer-VCC_SENSE" (solid, remove dead copper, pour order 123): 1365,3036 1365,2830 1448.29,2746.71 1652.3,2746.71 1757.01,2642 2006,2642 2035,2671 2035,3412 1990.79,3456.21 1458.79,3456.21 1389,3526 1389,3633 1347,3675 987,3675 944,3632 931.02,3619.02 931.02,3426.98 1048,3310 1338,3310 1376,3272 1448,3200 1448,3117 1365,3034
GND on BOTTOM "Top Layer-GND" (solid, remove dead copper, pour order 125): -82.6,3954 2125.61,3954 2182.4,3897.21 2182.4,-10.21 2092.61,-100 62.19,-100 -82.6,44.79
VBAT_CC on PWR "Bottom Layer-VBAT_CC" (solid, remove dead copper, pour order 119): 648.12,987.54 662.66,973 831,973 861,1003 861,1408 878,1425 1159,1425 1169,1435 1169,1487 1193.91,1511.91 1242.09,1511.91 1263,1491 1263,1179.89 1295.89,1147 1457,1147 1468,1158 1468,1438 1547,1517 1594.21,1564.21 1594.21,2585.79 1516,2664 1157.8,2664 1116.8,2623 792,2623 749.77,2623 581.77,2455 164,2455 138,2429 138,1860 218,1780 400,1780 909,2289 947,2289 961,2275 982.28,2253.72 982.28,2069.23 777.09,1864.04 777.09,1780.91 789,1769 867,1769 896,1740 985,1651 985,1597.84 961.17,1574 827,1574 735,1482 689.99,1436.99 689.99,1169.42 648.12,1127.55
VCC_BRD on PWR "Bottom Layer-VCC_BRD" (solid, remove dead copper, pour order 118): 2159.48,1334.39 2160.08,2788.35 2079.21,2869.22 1704.21,2869.21 1609,2774 1609,2207 1609,1428.06 1749.09,1287.98 2113.07,1287.98
VCC_LDO_3V3 on PWR "Bottom Layer-VCC_LDO_3V3" (solid, remove dead copper, pour order 122): 370,2466 553,2466 601,2514 717,2630 1110,2630 1129,2649 1149.21,2669.21 1965.91,2669.21 2010,2713.3 2010,3890 1979.79,3920.21 -13.79,3920.21 -63,3871 -63,2511.82 -17.18,2466 369,2466
VDD_ANA on PWR "Bottom Layer-VDD_ANA" (solid, remove dead copper, pour order 116): 983.79,1011.46 988.64,1006.61 1013.94,1006.61 1019.71,1012.38 1019.71,1046.14 1030.46,1056.89 1338.79,1056.89 1393.68,1002 1454,1002 1470,1018 1470,1096 1429,1137 1286.31,1136.99 1254.94,1168.38 1254.94,1473.06 1233.29,1494.71 1197.33,1494.71 1179.21,1476.58 1179.21,1116.21 1162.81,1099.81 1026.71,1099.8 983.8,1056.89
GND on PWR "Bottom Layer-GND" (solid, remove dead copper, pour order 120): -90,2452 710.94,2452 990,2172.95 990,1680.45 990,1415 1158,1415 1165.33,1407.67 1165.33,1136.73 1313.22,988.8 1313.23,680.87 1067.33,680.87 910.42,523.96 60.04,523.96 -80,664 -94,678 -94,2429 -94,2448
GND on PWR "Bottom Layer-GND" (solid, remove dead copper, pour order 121): 2137,-100 2189,-48 2192,-45 2192,8 2192,1859 1625,1859 1597,1831 1597,1006.37 1427.84,837.21 1025.21,837.21 839,651 -76,651 -97,630 -97,-36 -57,-76 -33,-100
no net on M4 3D STEP Bottom "M4 3D STEP Bottom-No Net" (solid, pour order 126): 2155,180 ccw(c2095,180) 2095,240 ccw(c2095,180) 2035,180 ccw(c2095,180) 2095,120 ccw(c2095,180) 2155,180
no net on M4 3D STEP Bottom "M4 3D STEP Bottom-No Net" (solid, pour order 128): 60,145 ccw(c0,145) 0,205 ccw(c0,145) -60,145 ccw(c0,145) 0,85 ccw(c0,145) 60,145
no net on M4 3D STEP Bottom "M4 3D STEP Bottom-No Net" (solid, pour order 127): 2015,3505 ccw(c1955,3505) 1955,3565 ccw(c1955,3505) 1895,3505 ccw(c1955,3505) 1955,3445 ccw(c1955,3505) 2015,3505
GND on GND "Top Layer-GND" (solid, remove dead copper, pour order 115): -39,3958 2139,3958 2185,3912 2185,3745 2185,-10 2160,-35 2095,-100 65,-100 -65,30 -80,45 -80,193.67 -80,3917

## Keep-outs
BOTTOM:
  circle w0: c1328.37,1409.13 r16
  circle w0: c1578.43,1350.19 r16
  circle w0: c1545,1319 r16
  circle w0: c1358.78,1181.27 r16
  circle w0: c1324.35,1232.86 r16
Keep-Out Layer:
  circle w1: c0,145 r60
  circle w1: c2094.68,141.5 r60
  circle w1: c1955.31,3858 r70
  lines w1: 658.69,3940.94 ccw(c797.29,4160.92) 935.97,3941 2120,3941 cw(c2118.5,3876.5) 2183,3875 2183,2384 ccw(c2275.22,2325.9) 2183.03,2267.76 ; 658.69,3941 418.91,3941 409.22,3931.31 409.22,3848.48 cw(c381.5,3861.4) 353.79,3848.48 353.79,3931.31 344.1,3941 231.9,3941 222.21,3931.31 222.21,3848.48 cw(c194.5,3861.4) 166.78,3848.48 166.78,3931.31 157.09,3941 -20,3941 ccw(c-20,3878) -83,3878 -83,2074.19 cw(c-302.92,1935.5) -83,1796.81 -83,-20 ccw(c-20,-20) -20,-83 667.81,-83 667.81,-97.58 ; 1226.52,-97.58 1226.52,-83 2120,-83 ccw(c2120,-20) 2183,-20 2183,1796 cw(c2402.92,1934.69) 2182.94,2073.28 ; 2183,2073.28 2183,2268

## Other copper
TOP:
  region net NetC2_2: 938.26,536.06 837.91,536.06 837.91,492.36 938.26,492.36
  rectangle net GND: 1077.8,-82.28 1121.11,33.86
  rectangle net GND: 867.21,3337.21 895.71,3346.91
  rectangle net GND: 872,1112 1167.28,1407.28
  rectangle net NetC20_1: 296,2745 357,2811
  rectangle net GND: 1104.84,629.06 1140.23,647.05
  pour cut-out: 721.53,551.61 721.53,554.67 711.53,554.67 711.53,552.95 710.2,551.62 ccw(c718.95,542.8) 706.52,542.84 706.52,486.65 ccw(c716.37,486.65) 709.41,479.69 709.86,479.24 ccw(c715.73,485.11) 715.73,476.81 808.14,476.81 808.14,455.25 824.87,455.25 ccw(c824.88,514) 866.42,472.46 950.76,474.7 950.76,553.97 869.49,553.97 868.41,553.97 866.4,555.97 ccw(c824.88,514.45) 824.87,573.17 808.14,573.17 808.14,551.61
  pour cut-out: 772.5,75.2 1054,75.2 1054,55.51 1146.52,55.51 1146.52,-100 772.5,-100
  pour cut-out: 1076.92,536.35 1081.92,536.35 1081.92,534.27 1080.18,532.53 1079.06,532.53 1076.92,534.68
  pour cut-out: 1077.65,169.68 1077.65,211.34 1077.77,211.21 1121.27,211.21 1121.27,169.68
  pour cut-out: 1277.81,628.65 1277.81,584.65 1272.81,584.65 1272.81,628.65
  pour cut-out: 1232.81,628.65 1232.81,584.65 1237.81,584.65 1237.81,628.65
  pour cut-out: 1121.46,496.71 1121.46,491.71 1119.38,491.71 1117.64,493.45 1117.64,494.57 1119.79,496.71
  pour cut-out: 1077.65,248.74 1077.65,207.09 1077.77,207.21 1121.27,207.21 1121.27,248.74
  pour cut-out: 1081.96,456.71 1116.96,456.71 1116.96,51.74 1081.96,51.74
  pour cut-out: 183.09,3404.4 183.09,3381.57 185.35,3379.31 246.32,3379.31 254.14,3387.13 254.14,3401.35 245.79,3409.7 188.38,3409.7
  pour cut-out: 729.61,-100.02 772.47,-100.02 772.47,75.2 729.61,75.2
  pour cut-out: 588.34,35.91 598.09,35.91 599.41,37.23 599.41,78.9 588.67,89.64 545.38,89.64 528.91,73.18 528.91,34.15 538.81,24.25 548.72,24.25 560.37,35.91
  pour cut-out: 272.19,1938.19 309,1938.19 309,2004.93 299.24,2014.7 293.37,2014.7 293.37,1959.37
  pour cut-out: 442.2,1094.88 442.2,1100.94 458,1100.94 458,1073 445,1073 443.43,1072.93 441.87,1072.73 440.34,1072.39 438.84,1071.91 437.39,1071.31 436,1070.59 434.68,1069.74 433.43,1068.79 432.27,1067.73 432.14,1067.6 431.51,1067 430.82,1066.46 430.09,1065.99 429.32,1065.58 428.52,1065.24 427.69,1064.96 426.84,1064.77 425.97,1064.64 425.1,1064.6 424.23,1064.63 423.36,1064.73 422.51,1064.91 421.68,1065.17 420.87,1065.49 420.09,1065.89 419.35,1066.35 418.65,1066.87 418,1067.45 417.93,1067.53 407.65,1077.81 407.06,1078.45 406.52,1079.15 406.06,1079.88 405.65,1080.66 405.32,1081.46 405.06,1082.29 404.87,1083.15 404.75,1084.01 404.72,1084.88 404.75,1085.75 404.87,1086.62 405.06,1087.47 405.32,1088.3 405.65,1089.11 406.06,1089.88 406.52,1090.62 407.06,1091.31 407.65,1091.95 408.29,1092.54 408.98,1093.07 409.72,1093.54 410.49,1093.94 411.3,1094.28 412.13,1094.54 412.98,1094.73 413.84,1094.84 414.72,1094.88 442.2,1094.88
  pour cut-out: 831,1087.54 831.77,1086.77 1173.76,1086.77 1173.76,1129.22 1197.17,1129.22 1197.17,1428 831,1428
  pour cut-out: 366.36,1992.7 367.25,1991.81 544.63,1991.81 544.63,2204.37 544,2205 369,2205 364,2200 365.09,2198.91 365.09,1994.19
  pour cut-out: 650,1493 650,1648.15 670.07,1668.22 721.2,1668.22 736.21,1653.21 736.21,1579.21
  pour cut-out: 986.17,914.1 1016.44,944.36 1016.44,1499 656,1499 650,1493 650,1363 648,1361 458,1361 453,1356 453,1063 460,1056 724,1056 730,1050 751.66,1050 769.25,1032.41 769.25,1002.53 760.93,994.21 734.94,994.2 730,989.27 730,723.54 965.05,723.54 965.05,914.1
  pour cut-out: 1319.57,839.93 1319.57,966 1245.27,966 1245.28,1402.72 1179,1469 1042,1469 942,1569 942,1765 947,1770 1612,1770 1612,839.93
  pour cut-out: 1295.21,1753.21 1302.21,1746.21 1565.21,1746.21 1575,1756 1575,1854 1538,1891 1335,1891 1295.21,1851.21
  pour cut-out: 1946.07,1679.22 1946.07,1629.99 1994.32,1629.99 1994.32,1679.22
  pour cut-out: 953.26,492.21 953.26,536.21 948.26,536.21 948.26,492.21
  region net NetC9_1: 1053.85,967.78 1054.27,965.42 1056.34,961.71 1060.69,949.34 1062,946.47 1066.59,946.51 1067.36,951.83 1068.76,967.41
  region net NetC10_1: 1101.76,967.78 1101.34,965.42 1099.27,961.71 1094.92,949.34 1093.61,946.47 1089.02,946.51 1088.25,951.83 1086.85,967.41
  region net NetC6_2: 1077.81,912.93 1075.15,912.93 1070.69,899.09 1084.89,899.09 1080.65,912.9
  pour cut-out: 603.58,556.02 603.58,625.19 600.39,628.38 596.07,628.38 595.42,627.73 595.42,557.88 597.52,555.77 603.33,555.77
  text "1" at 116,-60.63 h50
  text ".layer_Name" at -466,-1142 h60
GND:
  pour cut-out: 721.53,551.61 721.53,554.67 711.53,554.67 711.53,552.95 710.2,551.62 ccw(c718.95,542.8) 706.52,542.84 706.52,486.65 ccw(c716.37,486.65) 709.41,479.69 709.86,479.24 ccw(c715.73,485.11) 715.73,476.81 808.14,476.81 808.14,455.25 824.87,455.25 ccw(c824.88,514) 866.42,472.46 950.76,474.7 950.76,553.97 869.49,553.97 868.41,553.97 866.4,555.97 ccw(c824.88,514.45) 824.87,573.17 808.14,573.17 808.14,551.61
  pour cut-out: 721.53,476.81 721.53,472.75 711.53,472.75 711.53,475.47 710.89,476.11 cw(c721.43,486.65) 706.52,486.65 ccw(c716.37,486.65) 709.41,479.69 709.86,479.24 ccw(c715.73,485.11) 715.73,476.81
  pour cut-out: 729.61,-100.02 772.5,-100.02 772.5,75.2 729.61,75.2
  pour cut-out: 452.71,2851.1 460.19,2851.1 460.19,2836.9 452.71,2836.9
  pour cut-out: 772.5,75.2 1054,75.2 1054,55.51 1146.52,55.51 1146.52,-100 772.5,-100
  text "2" at 116,-60.63 h50
  text ".layer_Name" at -466,-1142 h60
PWR:
  pour cut-out: 1151.77,1036.58 1159.79,1028.56 1189.35,1028.56 1197.77,1036.98 1197.77,1049.19 1189.78,1057.18 1035.55,1057.18 1019.77,1041.41 1019.77,1002.75 1014.48,997.46 1041.49,997.46 1080.62,1036.58
  pour cut-out: 729.61,-100.02 772.5,-100.02 772.5,75.2 729.61,75.2
  pour cut-out: 709.96,1745.76 709.96,1716.17 721.78,1704.35 738.05,1704.35 750.89,1717.19 750.89,1744.62 743.36,1752.14 716.34,1752.14
  pour cut-out: 606.4,1750.48 606.4,1720.89 618.22,1709.07 634.49,1709.07 647.33,1721.9 647.33,1749.33 639.8,1756.86 612.78,1756.86
  pour cut-out: 960.47,1597.86 945.04,1597.57 940.23,1593.22 940.3,1579.01 950.57,1568.74 956.74,1568.74 967.31,1579.32 967.31,1591.02
  pour cut-out: 892.44,1742.47 897.29,1747.31 903.55,1741.23 903.55,1739.19 899.05,1734.7
  pour cut-out: 279.51,3646.94 282.09,3646.94 282.09,3632.75 279.51,3632.75
  pour cut-out: 313.29,3714.74 317.74,3710.97 310.31,3703.53 307.95,3705.9
  pour cut-out: 273.71,3727.1 276.29,3727.1 276.29,3712.9 273.71,3712.9
  pour cut-out: 270.21,2464.21 270.21,2445.21 271.21,2444.21 631.21,2444.21 641.48,2454.48 633.75,2462.21 272.21,2462.21
  pour cut-out: -24.68,-75 -40,-75 -80,-35 -80,-6.63 -70.68,-6.63 -70.05,-10.91 -68.91,-16.9 -67.24,-22.78 -65.07,-28.49 -62.41,-33.99 -59.29,-39.23 -55.71,-44.18 -51.72,-48.8 -47.34,-53.06 -42.61,-56.92 -37.56,-60.35 -32.23,-63.33 -27.75,-65.39 -24.68,-66.67 -24.68,-75
  pour cut-out: 108.61,1690.91 112.11,1694.41 189.21,1694.41 213.91,1669.71 213.91,1659.01 203.9,1649 112.53,1649 108.51,1653.01 108.61,1653.11
  pour cut-out: 708.31,2644.21 712.81,2639.71 725.01,2639.71 727.51,2642.21 727.51,2665.73 723.24,2670 713.4,2670 708.31,2664.91
  pour cut-out: 1291.9,3146.41 1290.35,3154.22 1285.93,3160.83 1279.32,3165.25 1271.51,3166.8 1263.71,3165.25 1257.09,3160.83 1252.67,3154.22 1251.12,3146.41 1252.67,3138.61 1257.09,3131.99 1263.71,3127.57 1271.51,3126.02 1279.32,3127.57 1285.93,3131.99 1290.35,3138.61 1291.9,3146.41
  pour cut-out: 772.5,75.2 1054,75.2 1054,55.51 1146.52,55.51 1146.52,-100 772.5,-100
  pour cut-out: 661.05,1143.2 661.05,1106.31 682.04,1085.32 694.13,1085.32 704.15,1095.33 704.15,1145.27 694.13,1155.29 673.14,1155.29
  pour cut-out: 754.47,1939.86 739.04,1939.57 734.23,1935.22 734.3,1921.01 744.57,1910.74 753.17,1910.74 761.31,1918.88 761.31,1933.02
  pour cut-out: 986.02,838.04 992.86,844.88 1014.32,844.88 1033.48,825.72 1033.48,812.17 1025.35,804.04 1010.08,804.04 986.02,828.1
  pour cut-out: 1142.97,819.23 1181.53,819.23 1188.69,826.39 1216.28,826.39 1221.69,820.97 1221.69,769.99 1218.2,766.5 1142.97,766.5
  pour cut-out: 1188.55,847.65 1196.95,839.24 1211.93,839.24 1217.15,844.45 1266.28,844.45 1284.72,862.9 1284.72,891.66 1278.77,897.61 1238.51,897.61
  pour cut-out: 1179.11,1054.09 1179.11,1048.55 1247.77,1048.55 1255.5,1056.28 1255.5,1078.2 1242.56,1091.14 1216.17,1091.14
  text "3" at 116,-60.63 h50
  text ".layer_Name" at -466,-1142 h60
